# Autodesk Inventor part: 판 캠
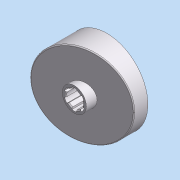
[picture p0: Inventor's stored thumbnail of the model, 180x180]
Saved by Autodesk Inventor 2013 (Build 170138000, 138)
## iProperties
Company: 한국ATC센터
Created: 2012-05
Part Number: 판 캠
Document SubType Name: 모델링
Designer: KYOUNG IL JANG
Mass: 681.586 g
Surface Area: 331.303 cm^2
Volume: 86.8262 cm^3
Density: 7.85 g/cm^3
Material: 강
변환 표준: STEP AP214IS
파일 이름: C:\Users\SeoGD\Desktop\?쒗뿕\??stp
전처리기: Build: 253, Release: 2010 SP1 - Date: Wed 07/29/2009
전송 단위: 밀리미터
불확실성: 0.01
Author: KYOUNG IL JANG
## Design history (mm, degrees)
node "작업 평면4"
sketch "스케치1"
  geometry: C1 r 44.5 at (0, 0); 1 further point
  constraints: 1 centre point, 1 coincident
  dimensions: "d25" = 89 diameter of C1
extrude "돌출1" new body sketch "스케치1" distance "d1" = 40; taper "d2" = 0 deg
sketch "스케치2"
  geometry: L1 (-44.5, 15)-(44.5, 38.847); L2 (-44.5, 0)-(-44.5, 40) reference; L3 (-44.5, 40)-(44.5, 40) reference; L4 (44.5, 0)-(44.5, 40) reference; 1 further point
  constraints: 2 end point, 2 point on line
  dimensions: "d26" = 15 distance of L2.start L1.start; "d27" = 75 deg angle of L1 L2
extrude "돌출2" cut sketch "스케치2" stored distance "d5" = 40; taper "d6" = 0 deg
node "작업 평면1"
sketch "스케치3"
  geometry: C1 r 13 at (0, 0); 1 further point
  constraints: 1 centre point, 1 coincident
  dimensions: "d9" = 26 diameter of C1
extrude "돌출3" join sketch "스케치3" distance "d10" = 38; taper "d11" = 0 deg
hole "구멍1" diameter "d14" = 18; stored, may be unused: countersink angle "d18" = 90 deg, drill point angle "d20" = 118 deg; dims "d12" = 10, "d13" = 10, "d15" = 6, "d16" = 4, "d17" = 2, "d19" = 8
feature "쉘2" dims "d29" = 5
sketch "스케치6"
  geometry: C1 r 17.5 at (0, 0); C2 r 14 at (0, 0) reference; 1 further point
  constraints: 1 centre point, 1 coincident
  dimensions: "d28" = 35 diameter of C1
extrude "돌출4" join sketch "스케치6" stored distance "d30" = 38; taper "d31" = 0 deg
fillet "모깎기1" dims "d32" = 3
chamfer "모따기1" distance "d21" = 1; stored, may be unused: second distance "d22" = 2, angle "d23" = 45 deg
sketch "스케치7"
  geometry: L1 (-12.374, 12.374)-(-27.931, 27.931); A1 r 39.5 centre (0, 0) between (-27.931, 27.931) and (0, 39.5) reference; 2 further points
  constraints: 2 end point, 2 point on circle, 1 point on line, 1 vertical alignment, 2 other
  dimensions: "d33" = 45 deg dimension on point (0, 0) L1.start A1.end
feature "리브1" sketch "스케치7" dims "d34" = 5, "d35" = 1, "d36" = 0
fillet "모깎기2" dims "d37" = 3
sketch "스케치8"
  geometry: L1 (2.5, 10.712)-(2.5, 8.646); L2 (-2.5, 10.712)-(-2.5, 8.646); A1 r 11 centre (0, 0) between (2.5, 10.712) and (-2.5, 10.712); A2 r 9 centre (0, 0) between (2.5, 8.646) and (-2.5, 8.646) reference; 1 further point
  constraints: 4 end point, 4 point on circle, 2 parallel, 1 centre point, 1 coincident, 1 vertical
  dimensions: "d41" = 22 diameter of A1; "d42" = 5 distance between parallel lines of L1 L2
extrude "돌출5" cut sketch "스케치8" stored distance "d43" = 38; taper "d44" = 0 deg
fillet "모깎기3" dims "d48" = 1
node "솔리드1"
node "솔리드 본체"
node "곡면 본체"
pattern_circular "원형 패턴1" dims angle "d39" = 360 deg
pattern_circular "원형 패턴2" dims angle "d46" = 360 deg
node "솔리드2"
